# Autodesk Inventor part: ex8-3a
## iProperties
Author: Administrator
Created: 2001-03
Part Number: ex8-3a
Document SubType Name: Modeling
Designer: Administrator
Control State: 0
Master: False
Checked Out: False
PropertySet Name: Design Tracking Control
Shininess: 20.0
Length Units: 11272
Angle Units: 11286
Time Units: 11279
Mass Units: 11290
Length Display Precision: 3
Angle Display Precision: 2
Compacted: False
PropertySet Name: _Private Model Information
Density: 0.0
Volumn: 0.0
Area: 0.0
PropertySet Name: Model Information
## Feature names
1. Extrusion1
2. Extrusion2
